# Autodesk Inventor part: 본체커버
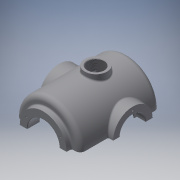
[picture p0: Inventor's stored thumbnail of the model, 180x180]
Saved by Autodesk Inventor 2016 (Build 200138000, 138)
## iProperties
Created: 2016-02
Part Number: 본체커버
Material: 알루미늄 6061
Document SubType Name: Modeling
Designer: mduedu
Density: 2.71 g/cm^3
Appearance: 기본값
Mass: 1187.07 g
Surface Area: 904.867 cm^2
Volume: 438.034 cm^3
Author: mduedu
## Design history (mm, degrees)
sketch "스케치2"
  geometry: L1 (0, 90)-(0, -90); L2 (65, -65.993)-(65, 90); L3 (65, 90)-(0, 90); A1 r 100 centre (0, 10) between (0, -90) and (65, -65.993); 2 further points
  constraints: 6 end point, 2 point on circle, 1 centre point, 1 coincident, 1 horizontal, 1 midpoint, 1 parallel, 1 point on line, 1 vertical
  dimensions: "d3" = 180 distance of L1.start L1.end; "d5" = 130 diameter of L2 L1; "d6" = 100 radius of A1
revolve "회전1" sketch "스케치2" stored, may be unused: angle "d7" = 90 deg
sketch "스케치3"
  geometry: C1 r 47.5 at (0, 0); 1 further point
  constraints: 1 centre point, 1 coincident
  dimensions: "d8" = 95 diameter of C1
extrude "돌출2" join sketch "스케치3" distance "d10" = 10; taper "d11" = 0 deg
sketch "스케치5"
  geometry: L1 (47.5, 100)-(47.5, 90) reference; L2 (47.5, 90)-(65, 90) reference; L3 (65, 90)-(65, -65.993) reference; L4 (-65, -65.993)-(-65, 90) reference; L5 (-65, 90)-(-47.5, 90) reference; L6 (-47.5, 90)-(-47.5, 100) reference; L7 (-47.5, 100)-(47.5, 100) reference; L8 (55, 75)-(55, -61.239); L9 (0, 75)-(55, 75); L10 (0, 75)-(0, -80); A1 r 100 centre (0, 10) between (-65, -65.993) and (0, -90) reference; A2 r 100 centre (0, 10) between (0, -90) and (65, -65.993) reference; A3 r 90 centre (0, 10) between (0, -80) and (55, -61.239); 1 further point
  constraints: 6 end point, 2 point on circle, 1 centre point, 1 parallel, 1 perpendicular, 1 point on line, 1 vertical
  dimensions: "d13" = 10 distance between parallel lines of L3 L8; "d14" = 10 radial gap between concentric circles of A3 A1; "d15" = 15 distance between parallel lines of L9 L2
revolve "회전2" sketch "스케치5" stored, may be unused: angle "d16" = 90 deg
hole "구멍1" diameter "d19" = 65; stored, may be unused: countersink angle "d23" = 90 deg, drill point angle "d25" = 118 deg; dims "d17" = 10, "d18" = 10, "d20" = 6, "d21" = 4, "d22" = 2, "d24" = 8
node "작업 평면1"
sketch "스케치6"
  geometry: L1 (47.5, 100)-(-47.5, 100) reference; C1 r 40 at (0, -7); 1 further point
  constraints: 1 centre point, 1 vertical alignment
  dimensions: "d27" = 80 diameter of C1; "d29" = 107 distance from line of C1.centre L1
extrude "돌출3" join sketch "스케치6" stored distance "d30" = 10; taper "d31" = 0 deg
hole "구멍2" diameter "d34" = 42; stored, may be unused: countersink angle "d38" = 90 deg, drill point angle "d40" = 118 deg; dims "d32" = 10, "d33" = 10, "d35" = 6, "d36" = 52, "d37" = 18, "d39" = 8
sketch "스케치7" dims "d41" = 65
  geometry: C1 r 40 at (0, 0) reference; 3 further points
  constraints: 2 vertical alignment, 1 coincident, 2 other
hole "구멍3" sketch "스케치7" at (0, 32.5) diameter "d43" = 3.242; stored, may be unused: countersink angle "d47" = 90 deg, drill point angle "d49" = 118 deg; dims "d44" = 11, "d45" = 13, "d46" = 18, "d48" = 13
sketch "스케치8" dims "d53" = 80
  geometry: 3 further points
  constraints: 2 vertical alignment, 1 coincident, 2 other
hole "구멍4" sketch "스케치8" at (0, -40) diameter "d56" = 3.242; stored, may be unused: countersink angle "d60" = 90 deg, drill point angle "d62" = 118 deg; dims "d57" = 11, "d58" = 13, "d59" = 18, "d61" = 13
fillet "모깎기1" dims "d66" = 10
fillet "모깎기2" dims "d67" = 3
fillet "모깎기3" dims "d68" = 0.3
chamfer "모따기1" distance "d69" = 1; stored, may be unused: second distance "d70" = 2, angle "d71" = 45 deg
node "작업 평면5"
sketch "스케치10"
  geometry: L1 (-50, 66)-(50, 66); L2 (50, 66)-(50, 50); L3 (50, 50)-(-50, 50); L4 (-50, 50)-(-50, 66); 2 further points
  constraints: 8 end point, 2 horizontal, 2 vertical, 1 midpoint, 1 vertical alignment
  dimensions: "d177" = 50 distance from line of L3 point (0, 0); "d178" = 100 distance of L1.start L1.end; "d179" = 16 distance of L3.end L1.start
extrude "돌출5" join sketch "스케치10" stored distance "d84" = 10; taper "d85" = 0 deg
sketch "스케치21" dims "d180" = 220, "d182" = 130
  geometry: L1 (65, 58)-(-65, 58); L2 (-65, 58)-(-65, -32); L3 (-65, -32)-(65, -32); L4 (65, -32)-(65, 58); L5 (50, 50)-(50, 66) reference; 4 further points
  constraints: 8 end point, 3 horizontal alignment, 3 midpoint, 2 parallel, 1 horizontal, 1 perpendicular, 1 vertical alignment, 4 other
extrude "돌출13" join sketch "스케치21" distance "d183" = 10; taper "d184" = 0 deg
sketch "스케치11"
  geometry: L1 (-65, 80)-(-65, -61.239) reference; L2 (-100, -97)-(-100, -32) reference; L3 (-65, -42.793)-(-100, -63); L4 (-100, -97)-(-110, -97) reference; 1 further point
  constraints: 2 end point, 2 point on line
  dimensions: "d185" = 34 distance from line of L3.end L4; "d186" = 120 deg angle of L2 L3
feature "리브1" sketch "스케치11" dims "d88" = 1, "d89" = 16, "d90" = 0, "d91" = 0, "d92" = 1, "d93" = 1
fillet "모깎기12"
fillet "모깎기13"
fillet "모깎기16" dims "d167" = 3
fillet "모깎기18"
fillet "모깎기17" dims "d168" = 3
fillet "모깎기19" dims "d187" = 3
node "작업 평면6"
sketch "스케치19"
  geometry: L1 (75, -47)-(75, 33) reference; L2 (-75, -47)-(-75, 33) reference; L3 (75, -7)-(-75, -7); C1 r 22.5 at (0, -7); 1 further point
  constraints: 3 midpoint, 2 end point, 1 centre point
  dimensions: "d149" = 45 diameter of C1
extrude "돌출11" join sketch "스케치19" stored distance "d150" = 10; taper "d151" = 0 deg
hole "구멍6" diameter "d154" = 33.376; stored, may be unused: countersink angle "d158" = 90 deg, drill point angle "d160" = 118 deg; dims "d155" = 6, "d156" = 4, "d157" = 2, "d159" = 8, "d190" = 10, "d191" = 10
fillet "모깎기11" dims "d161" = 3
chamfer "모따기3" distance "d164" = 1; stored, may be unused: second distance "d165" = 2, angle "d166" = 45 deg
sketch "스케치22" dims "d189" = 20
  geometry: L1 (-10, -123)-(10, -123); L2 (10, -123)-(10, -103); L3 (10, -103)-(-10, -103); L4 (-10, -103)-(-10, -123); A1 r 65 centre (0, -58) between (-65, -58) and (65, -58) reference; 2 further points
  constraints: 8 end point, 2 parallel, 1 horizontal, 1 horizontal alignment, 1 midpoint, 1 perpendicular, 1 tangent, 1 vertical alignment, 2 other
  dimensions: "d193" = 30 dimension on L1
extrude "돌출14" cut sketch "스케치22" stored distance "d194" = 10; taper "d195" = 0 deg
fillet "모깎기21" dims "d196" = 3
feature "분할1"
node "솔리드2"
pattern_circular "원형 패턴1" dims angle "d51" = 360 deg
mirror "대칭1"
pattern_circular "원형 패턴2" dims angle "d64" = 360 deg
node "절단 모서리 투영1"
other parameters: "d26" = 75, "d136" = 175
